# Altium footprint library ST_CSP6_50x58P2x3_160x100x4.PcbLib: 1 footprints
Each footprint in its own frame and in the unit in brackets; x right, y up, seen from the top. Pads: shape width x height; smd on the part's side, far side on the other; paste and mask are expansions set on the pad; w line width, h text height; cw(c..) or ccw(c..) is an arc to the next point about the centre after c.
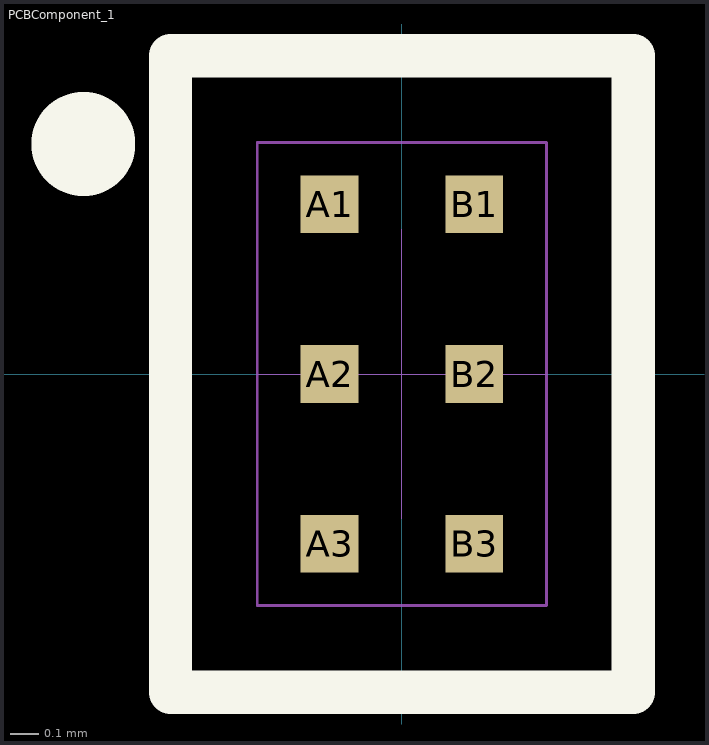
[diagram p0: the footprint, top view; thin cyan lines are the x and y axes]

## PCBComponent_1 [mm]
pads (6):
  rect 0.2x0.2 smd paste+0 mask+0.05: A1(-0.25,0.587) A2(-0.25,0) A3(-0.25,-0.587) B1(0.25,0.587) B2(0.25,0) B3(0.25,-0.587)
Top Overlay:
  circle w0.3: c-1.101,0.795 r0.03
  lines w0.15: -0.8,-1.1 0.8,-1.1 0.8,1.1 -0.8,1.1 -0.8,-1.1
Mechanical 15:
  lines w0.001: -0.5,0 0.5,0 ; 0,-0.5 0,0.5
  lines w0.01: -0.5,-0.8 0.5,-0.8 0.5,0.8 -0.5,0.8 -0.5,-0.8
3D body: height 0.45, standoff 0, extent -0.5,-0.8 0.5,0.8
